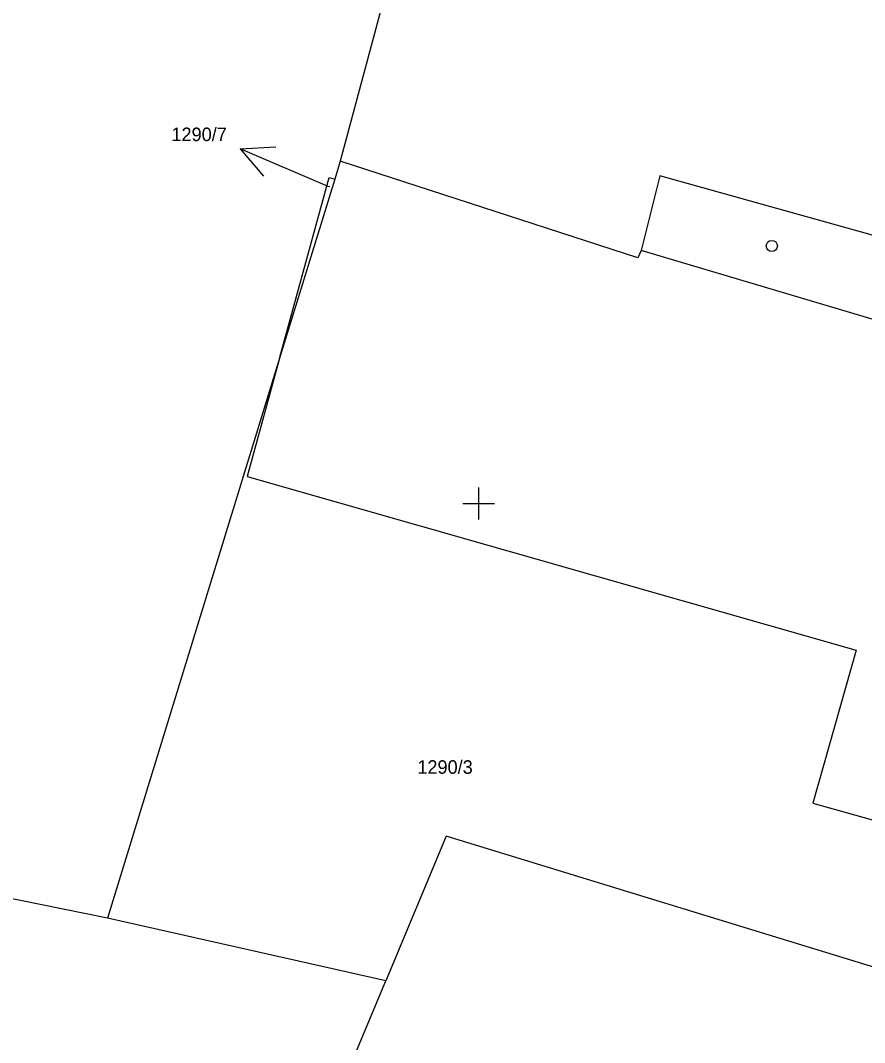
# Model space of a CAD drawing. Extents: x -702257 to -701487, y -1009871 to -1008841.
# Drawn here: x -701764.39 to -701737.89, y -1009241.91 to -1009209.84 of the extents above; entities that cross this region are included whole.
import ezdxf

# ---------------------------------------------------------------- set-up
doc = ezdxf.new("R2010")
doc.units = 0
for name, color, linetype in [('Z_hektometricka_sit', 7, 'Continuous'), ('Z_katastr_cisla_pozemkova', 7, 'Continuous'), ('Z_katastr_cisla_stavebni', 7, 'Continuous'), ('Z_katastr_hranice', 7, 'Continuous'), ('Z_katastr_parcelni_cislo_odkaz', 7, 'Continuous'), ('Z_katastr_vnitrni_kresba', 7, 'Continuous'), ('Z_katastr_znacky_budov', 7, 'Continuous')]:
    doc.layers.add(name, color=color, linetype=linetype)

msp = doc.modelspace()

# ---------------------------------------------------------------- linework, layer by layer
at = {"layer": 'Z_hektometricka_sit'}
for p, q in [((-701750, -1009224.5), (-701750, -1009225.5)), ((-701750, -1009224.5), (-701750, -1009225.5)), ((-701750.5, -1009225), (-701749.5, -1009225)), ((-701750.5, -1009225), (-701749.5, -1009225))]:
    msp.add_line(p, q, dxfattribs=at)
at = {"layer": 'Z_katastr_hranice'}
for p, q in [((-701751.94, -1009205.31), (-701754.35, -1009214.26)), ((-701754.35, -1009214.26), (-701754.52, -1009214.82)), ((-701745, -1009217.29), (-701754.35, -1009214.26)), ((-701756.24, -1009220.41), (-701754.69, -1009214.77)), ((-701754.69, -1009214.77), (-701754.52, -1009214.82)), ((-701754.52, -1009214.82), (-701756.24, -1009220.41)), ((-701744.9, -1009217.06), (-701745, -1009217.29)), ((-701735.88, -1009219.74), (-701744.9, -1009217.06)), ((-701756.24, -1009220.41), (-701761.65, -1009238.01)), ((-701756.24, -1009220.41), (-701757.27, -1009224.15)), ((-701757.27, -1009224.15), (-701738.15, -1009229.6)), ((-701761.65, -1009238.01), (-701811.33, -1009227.89)), ((-701738.15, -1009229.6), (-701739.51, -1009234.4)), ((-701739.51, -1009234.4), (-701729.74, -1009237.16)), ((-701751.02, -1009235.44), (-701752.91, -1009239.98)), ((-701730.88, -1009241.61), (-701751.02, -1009235.44)), ((-701752.91, -1009239.98), (-701761.65, -1009238.01)), ((-701753.82, -1009242.15), (-701752.91, -1009239.98))]:
    msp.add_line(p, q, dxfattribs=at)
at = {"layer": 'Z_katastr_parcelni_cislo_odkaz'}
for p, q in [((-701757.482, -1009213.877), (-701756.365, -1009213.808)), ((-701754.72, -1009215.05), (-701757.482, -1009213.877)), ((-701757.482, -1009213.877), (-701756.756, -1009214.73)), ((-701754.67, -1009215.07), (-701754.72, -1009215.05))]:
    msp.add_line(p, q, dxfattribs=at)
at = {"layer": 'Z_katastr_vnitrni_kresba'}
for p, q in [((-701744.31, -1009214.72), (-701744.9, -1009217.06)), ((-701736.1, -1009217.01), (-701744.31, -1009214.72))]:
    msp.add_line(p, q, dxfattribs=at)
at = {"layer": 'Z_katastr_znacky_budov'}
msp.add_circle((-701740.797, -1009216.919), 0.175, dxfattribs=at)

# ---------------------------------------------------------------- texts
at = {"layer": 'Z_katastr_cisla_pozemkova'}
msp.add_text('1290/3', height=0.425, dxfattribs=at).set_placement((-701751.924, -1009233.48))
at = {"layer": 'Z_katastr_cisla_stavebni'}
msp.add_text('1290/7', height=0.425, dxfattribs=at).set_placement((-701759.644, -1009213.631))

doc.saveas('drawing.dxf')
